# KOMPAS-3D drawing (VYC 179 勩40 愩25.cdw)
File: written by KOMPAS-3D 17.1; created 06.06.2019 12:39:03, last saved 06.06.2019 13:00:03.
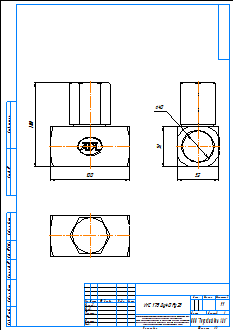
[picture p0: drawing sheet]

Sheet 1: A3, portrait

Title block, sheet 1: name: VYC 179 Ду40 Ру25; material: Внимание! Данный продукт является объектом авторского права ООО «Торговый Дом АДЛ». / Запрещается изменение, копирование, распространение / (в том числе путем копирования на другие сайты и ресурсы в Интернете) / или любое иное использование информации и объектов без предварительного / согласия правообладателя (ООО «Торговый Дом АДЛ»).; sheets: 1; organisation: ООО "Торговый дом АДЛ"; sheet format: A3; stored path: \\adlc.lan\data\АДЛ_ПКД\3D-модели\Поставщики\VYC Industrial\VYC 179\KOMPAS 2D\VYC 179 Ду40 Ру25.cdw

Views: Вид 1, Проекционный вид 2, Проекционный вид 3
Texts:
  user
Dimensions and other numbers on the sheet: 100; 108; 52; 40; 1:1; 1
